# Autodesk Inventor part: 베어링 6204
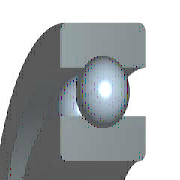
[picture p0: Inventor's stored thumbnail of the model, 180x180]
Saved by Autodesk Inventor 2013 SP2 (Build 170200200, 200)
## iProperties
IsCustomPart: 0
Created: 2009-02
Part Number: 베어링 6204
Material: 강, 연강
Description: 깊은 그루브 볼 베어링
Document SubType Name: Modeling
Standard: KS B 2023
Designer: KYOUNG IL JANG
Standards Organization: KS
Language: ko-KR
Size Designation: 6204 - 20 x 47 x 14
Categories: <MemberInstance><Categories><Category DisplayName="샤프트 부품" InternalName="7f7aeb1f-a693-4053-b835-cee3144e0d98" Mnemonic="SHFT"><Category DisplayName="베어링" Inter
Density: 7.86 g/cm^3
Mass: 104.255 g
Surface Area: 87.8912 cm^2
Volume: 13.264 cm^3
Author: KYOUNG IL JANG
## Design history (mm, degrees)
sketch "스케치" dims "d0" = 7.02 (= -0.26 x WD + 0.26 x BD)
  geometry: L1 (3.49, 16.75)-(10.51, 16.75); L2 (7, 16.75)-(7, 13.24); L3 (7, 16.75)-(7, 20.26); L4 (4.392, 14.401)-(0, 14.401); L5 (0, 10)-(14, 10); L6 (4.392, 19.099)-(0, 19.099); L7 (0, 23.5)-(14, 23.5); L8 (14, 10)-(14, 14.401); L9 (9.608, 14.401)-(14, 14.401); L10 (9.608, 19.099)-(14, 19.099); L11 (14, 23.5)-(14, 19.099); L12 (-1.4, 0)-(8.4, 0) reference; L13 (0, -0.3)-(0, 5.3) reference
  constraints: 22 end point, 4 point on line, 2 collinear, 2 perpendicular, 2 symmetric about line, 1 midpoint, 1 parallel, 14 other
  dimensions: "d9" = 20 diameter of L5 L12 (= WD); "d11" = 47 diameter of L7 L12 (= BD); "d12" = 14 distance between parallel lines of L8 L13 (= KB); "d13" = 28.802 diameter of L9 L12 (= 0.326 x BD + 0.674 x WD)
revolve "본체" stored, may be unused: angle "d6" = 90 deg
revolve "볼" stored, may be unused: angle "d7" = 90 deg
pattern_circular "IDS_ARRAYBALL[SIMPL:T]" dims angle "d3" = 360 deg
body "Solid1"
fillet "모깎기1" dims "d1" = 1 (= KRS)
other parameters: "WD" = 20 [user parameter; used in 5 equation terms], "BD" = 47 [user parameter; used in 5 equation terms], "KB" = 14 [user parameter; used in 1 equation term], "KRS" = 1 [user parameter; used in 1 equation term], "d4" = 0, "d5" = 0, "d8" = 0, "d14" = 0, "d15" = 0, "BBA" = 0 [user parameter], "BC0" = 6550000 [user parameter], "BC" = 1.27e+07 [user parameter], "BR" = 23.5 (= 0.5 x BD) [user parameter]
